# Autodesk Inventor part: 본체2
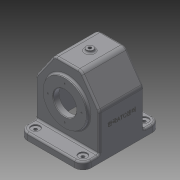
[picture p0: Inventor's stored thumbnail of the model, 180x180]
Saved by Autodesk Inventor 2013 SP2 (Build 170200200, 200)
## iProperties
Created: 2022-12
Part Number: 본체2
Material: Generic
Document SubType Name: Modeling
Designer: i
Density: 1 g/cm^3
Author: i
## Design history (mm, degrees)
sketch "스케치1"
  geometry: L1 (38.5, 55)-(-38.5, 55); L2 (-38.5, 55)-(-38.5, -55); L3 (-38.5, -55)-(38.5, -55); L4 (38.5, -55)-(38.5, 55); L5 (38.5, 55)-(-38.5, -55); L6 (-38.5, 55)-(38.5, -55); L7 (38.5, 55)-(83.5, 23.491); L8 (38.5, 55)-(93.435, 55); L9 (83.5, 23.491)-(83.5, -23.491); L10 (83.5, -23.491)-(38.5, -55); 1 further point
  constraints: 20 end point, 2 horizontal, 2 midpoint, 2 parallel, 2 perpendicular, 1 equal length
  dimensions: "d0" = 77 distance of L3.end L2.end; "d1" = 110 distance of L2.end L1.end; "d2" = 35 deg angle of L7 L8; "d4" = 125 deg angle of L9 L10; "d5" = 122 distance between parallel lines of L9 L2
extrude "돌출1" new body sketch "스케치1" stored distance "d6" = 77; taper "d7" = 0 deg
sketch "스케치2"
  geometry: L1 (-55, -38.5)-(55, -38.5) reference; C1 r 31 at (0, 26.5); 1 further point
  constraints: 1 centre point
  dimensions: "d8" = 62 diameter of C1; "d10" = 65 distance from line of C1.centre L1
extrude "돌출2" join sketch "스케치2" distance "d11" = 10; taper "d12" = 0 deg
sketch "스케치3"
  geometry: C1 r 31 at (0, 0) reference; C2 r 20 at (0, 0); 1 further point
  constraints: 1 centre point, 1 coincident
  dimensions: "d13" = 40 diameter of C2
extrude "돌출3" cut sketch "스케치3" stored distance "d14" = 15; taper "d15" = 0 deg
sketch "스케치4"
  geometry: L1 (-55, -38.5)-(55, -38.5) reference; C1 r 37.5 at (0, 26.5); 1 further point
  constraints: 1 centre point
  dimensions: "d16" = 75 diameter of C1; "d17" = 65 distance from line of L1 C1.centre
extrude "돌출4" join sketch "스케치4" distance "d18" = 5; taper "d19" = 0 deg
sketch "스케치5"
  geometry: C1 r 37.5 at (0, 0) reference; C2 r 20 at (0, 0); 1 further point
  constraints: 1 centre point, 1 coincident
  dimensions: "d20" = 40 diameter of C2
extrude "돌출6" cut sketch "스케치5" distance "d23" = 24; taper "d24" = 0 deg
sketch "스케치6"
  geometry: L1 (0, 0)-(0, 26); C1 r 31 at (0, 0) reference; 2 further points
  constraints: 2 end point, 1 coincident, 1 vertical
  dimensions: "d25" = 26 distance of L1.start L1.end
hole "구멍1" sketch "스케치6" at (0, 26) diameter "d26" = 2.459; stored, may be unused: countersink angle "d30" = 90 deg, drill point angle "d32" = 118 deg; dims "d27" = 6, "d28" = 4, "d29" = 2, "d31" = 8
sketch "스케치7"
  geometry: L1 (0, 0)-(0, 29); C1 r 37.5 at (0, 0) reference; 2 further points
  constraints: 2 end point, 1 coincident, 1 vertical
  dimensions: "d36" = 29 distance of L1.start L1.end
hole "구멍2" sketch "스케치7" at (0, 29) diameter "d37" = 2.459; stored, may be unused: countersink angle "d41" = 90 deg, drill point angle "d43" = 118 deg; dims "d38" = 6, "d39" = 4, "d40" = 2, "d42" = 8
sketch "스케치8"
  geometry: L1 (0, 0)-(77, 0) reference; L2 (77, 110)-(77, 0) reference; L3 (0, 110)-(77, 110) reference; L4 (0, 0)-(0, 110) reference; L5 (-28.5, 110)-(105.5, 110); L6 (105.5, 110)-(105.5, 0); L7 (105.5, 0)-(-28.5, 0); L8 (-28.5, 0)-(-28.5, 110); L9 (-28.5, 110)-(105.5, 0); L10 (105.5, 110)-(-28.5, 0); 1 further point
  constraints: 12 end point, 2 midpoint, 2 parallel, 1 horizontal, 1 perpendicular
  dimensions: "d47" = 134 distance of L6.end L7.end; "d48" = 110 distance of L5.end L6.end
extrude "돌출7" join sketch "스케치8" distance "d49" = 12; taper "d50" = 0 deg
fillet "모깎기1" dims "d51" = 14
sketch "스케치9"
  geometry: L1 (91.5, 0)-(77, 0) reference; L2 (77, -110)-(77, 0) reference; L3 (77, -110)-(91.5, -110) reference; L4 (105.5, -96)-(105.5, -14) reference; A1 r 14 centre (-14.5, -14) between (-14.5, 0) and (-28.5, -14) reference; A2 r 14 centre (-14.5, -96) between (-28.5, -96) and (-14.5, -110) reference; A3 r 14 centre (91.5, -14) between (105.5, -14) and (91.5, 0) reference; A4 r 14 centre (91.5, -96) between (91.5, -110) and (105.5, -96) reference; 5 further points
  constraints: 4 coincident
hole "구멍3" sketch "스케치9" at (-14.5, -14), (91.5, -14), (91.5, -96), (-14.5, -96) diameter "d52" = 5.5; stored, may be unused: countersink angle "d56" = 90 deg, drill point angle "d58" = 118 deg; dims "d53" = 6, "d54" = 15, "d55" = 2, "d57" = 8
sketch "스케치12"
  geometry: C1 r 6 at (38.5, 23.491); 1 further point
  constraints: 1 centre point, 1 coincident
  dimensions: "d69" = 12 diameter of C1
extrude "돌출10" join sketch "스케치12" distance "d70" = 4; taper "d71" = 0 deg
sketch "스케치13"
  geometry: C1 r 6 at (0, 0) reference; 1 further point
  constraints: 1 coincident
hole "구멍4" sketch "스케치13" at (0, 0) diameter "d72" = 5.188; stored, may be unused: countersink angle "d76" = 90 deg, drill point angle "d78" = 118 deg; dims "d73" = 12, "d74" = 15, "d75" = 2, "d77" = 8
fillet "모깎기2" dims "d84" = 10
fillet "모깎기3" dims "d85" = 3
chamfer "모따기1" distance "d86" = 1; stored, may be unused: second distance "d87" = 2, angle "d88" = 45 deg
fillet "모깎기4" dims "d89" = 3
sketch "스케치15"
  geometry: L1 (0, 0)-(106, 0) reference; L2 (14.5, 73.847)-(14.5, 15) reference; L3 (-14, 9)-(-14, 0) reference; 2 further points
  constraints: 1 other
  dimensions: "d90" = 50 distance from line of L1 point (53, 50); "d91" = 38.5 distance from line of point (53, 50) L2; "d94" = 28.5 distance between parallel lines of L2 L3 (derived)
feature "엠보싱1" sketch "스케치15" dims "d0" = 77, "d1" = 110, "d2" = 35 deg, "d4" = 125 deg, "d5" = 122, "d13" = 40, "d92" = 0.5, "d93" = 0
sketch "스케치14"
  geometry: L1 (-100.5, 91)-(-33.5, 91); L2 (-33.5, 91)-(-33.5, -9); L3 (-33.5, -9)-(-100.5, -9); L4 (-100.5, -9)-(-100.5, 91); L5 (-100.5, 91)-(-33.5, -9); L6 (-33.5, 91)-(-100.5, -9); C1 r 2.594 at (-67, 41) reference
  constraints: 12 end point, 2 midpoint, 2 parallel, 1 horizontal, 1 perpendicular
  dimensions: "d80" = 67 distance of L2.end L3.end; "d81" = 100 distance of L1.end L2.end
extrude "돌출11" cut sketch "스케치14" distance "d82" = 77; taper "d83" = 0 deg
node "솔리드1"
pattern_circular "원형 패턴1" dims angle "d34" = 360 deg
pattern_circular "원형 패턴2" dims angle "d45" = 360 deg
node "투영된 루프1"
